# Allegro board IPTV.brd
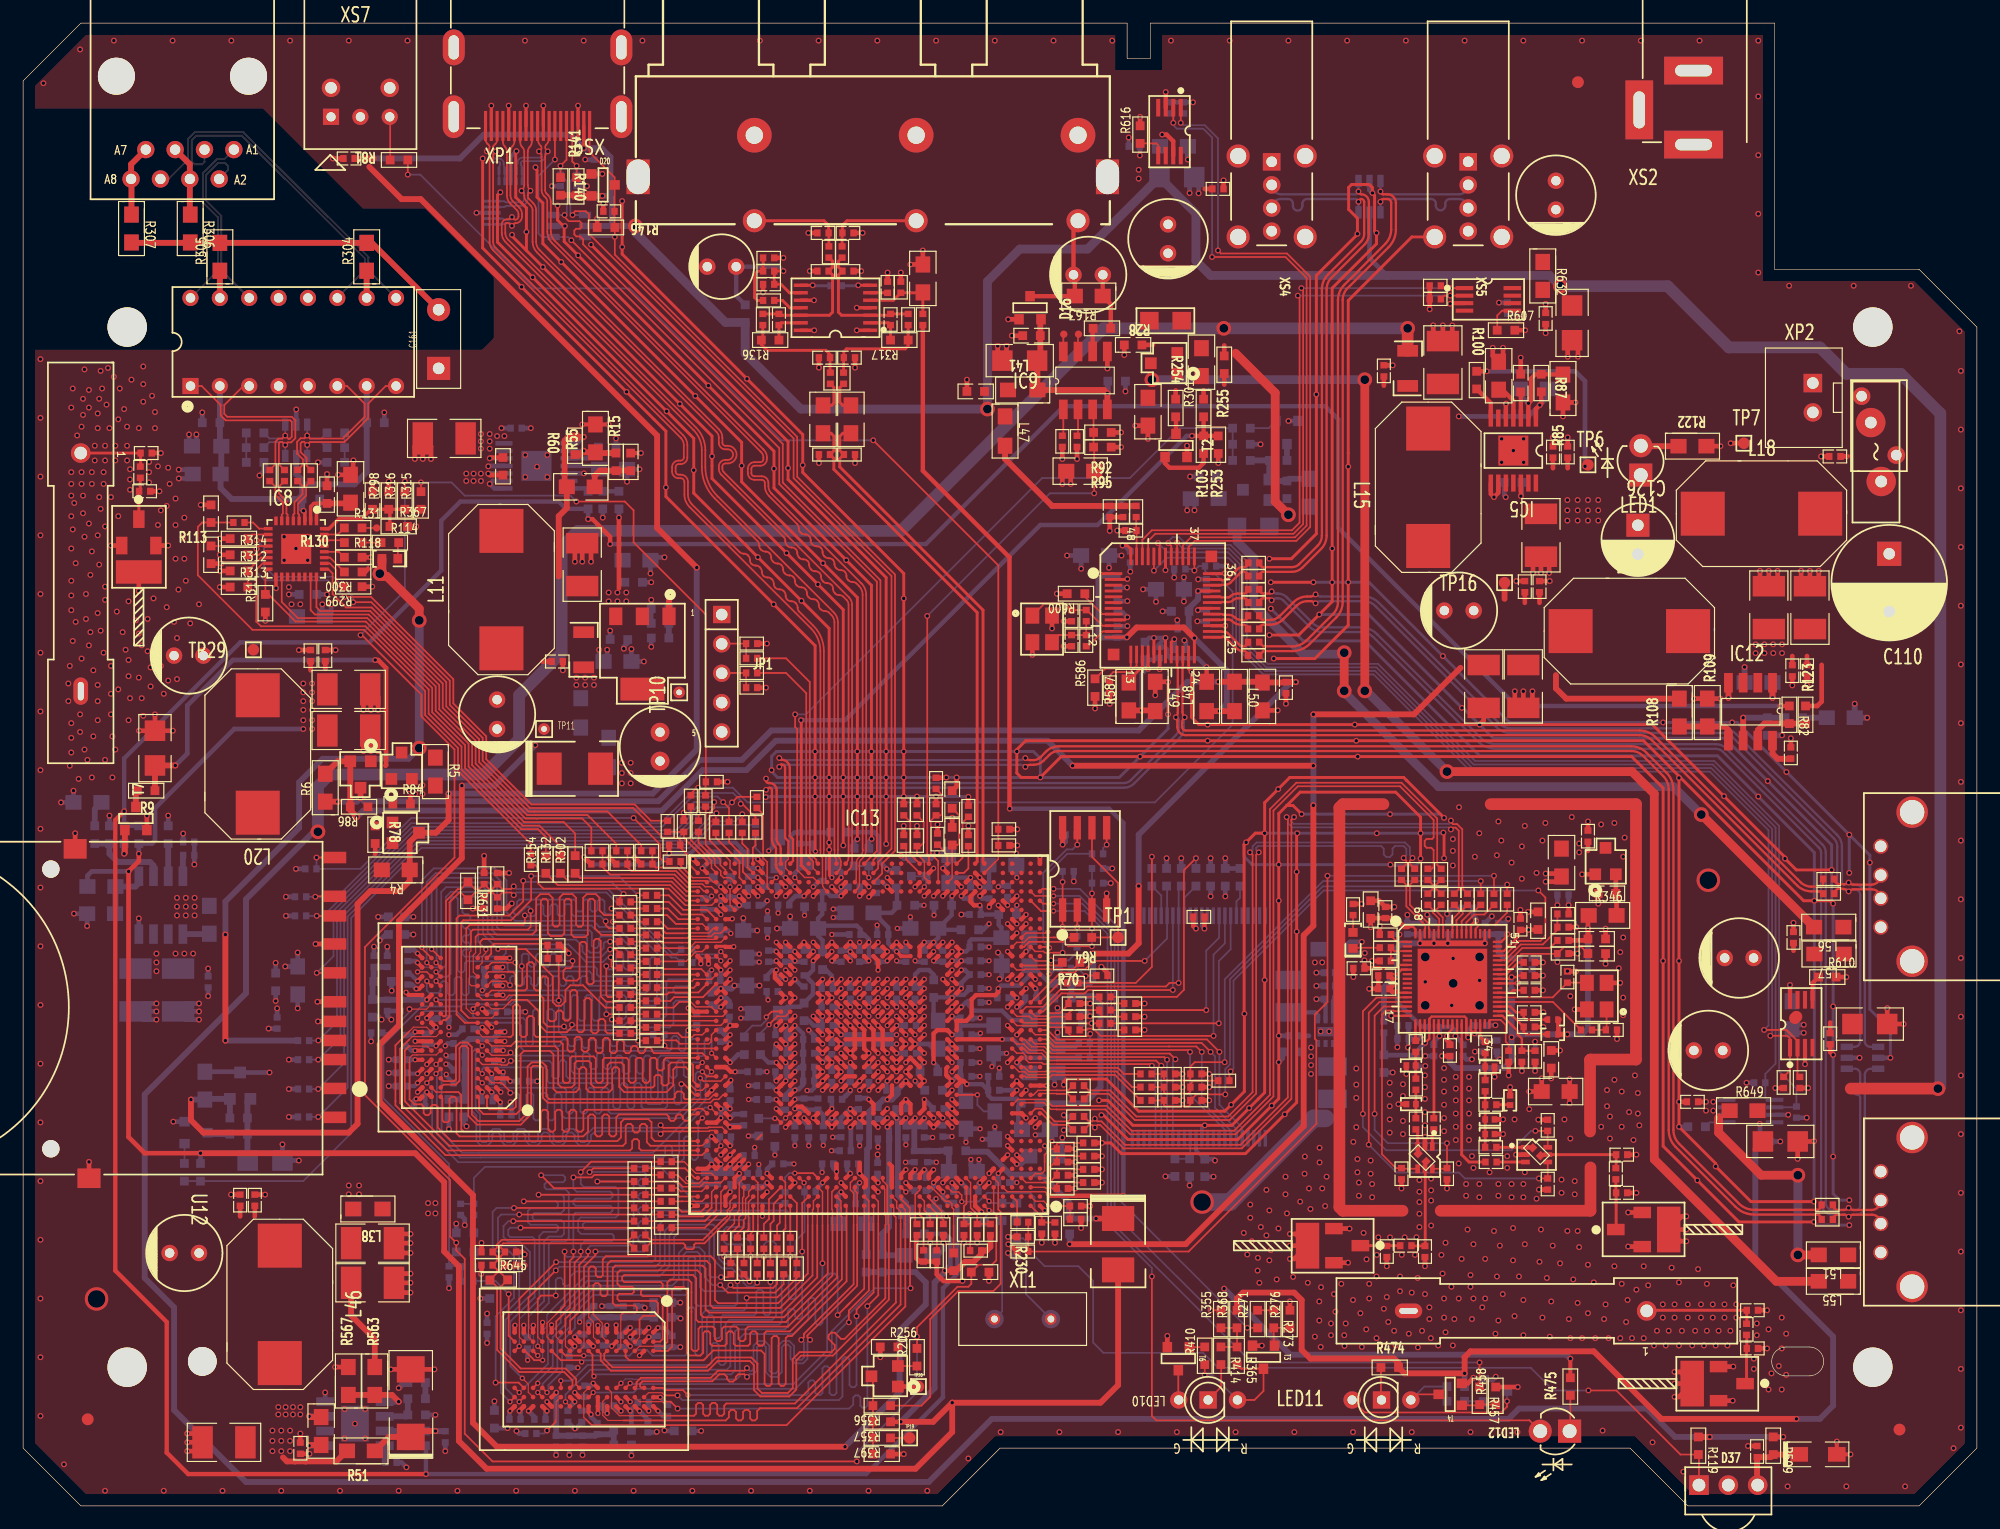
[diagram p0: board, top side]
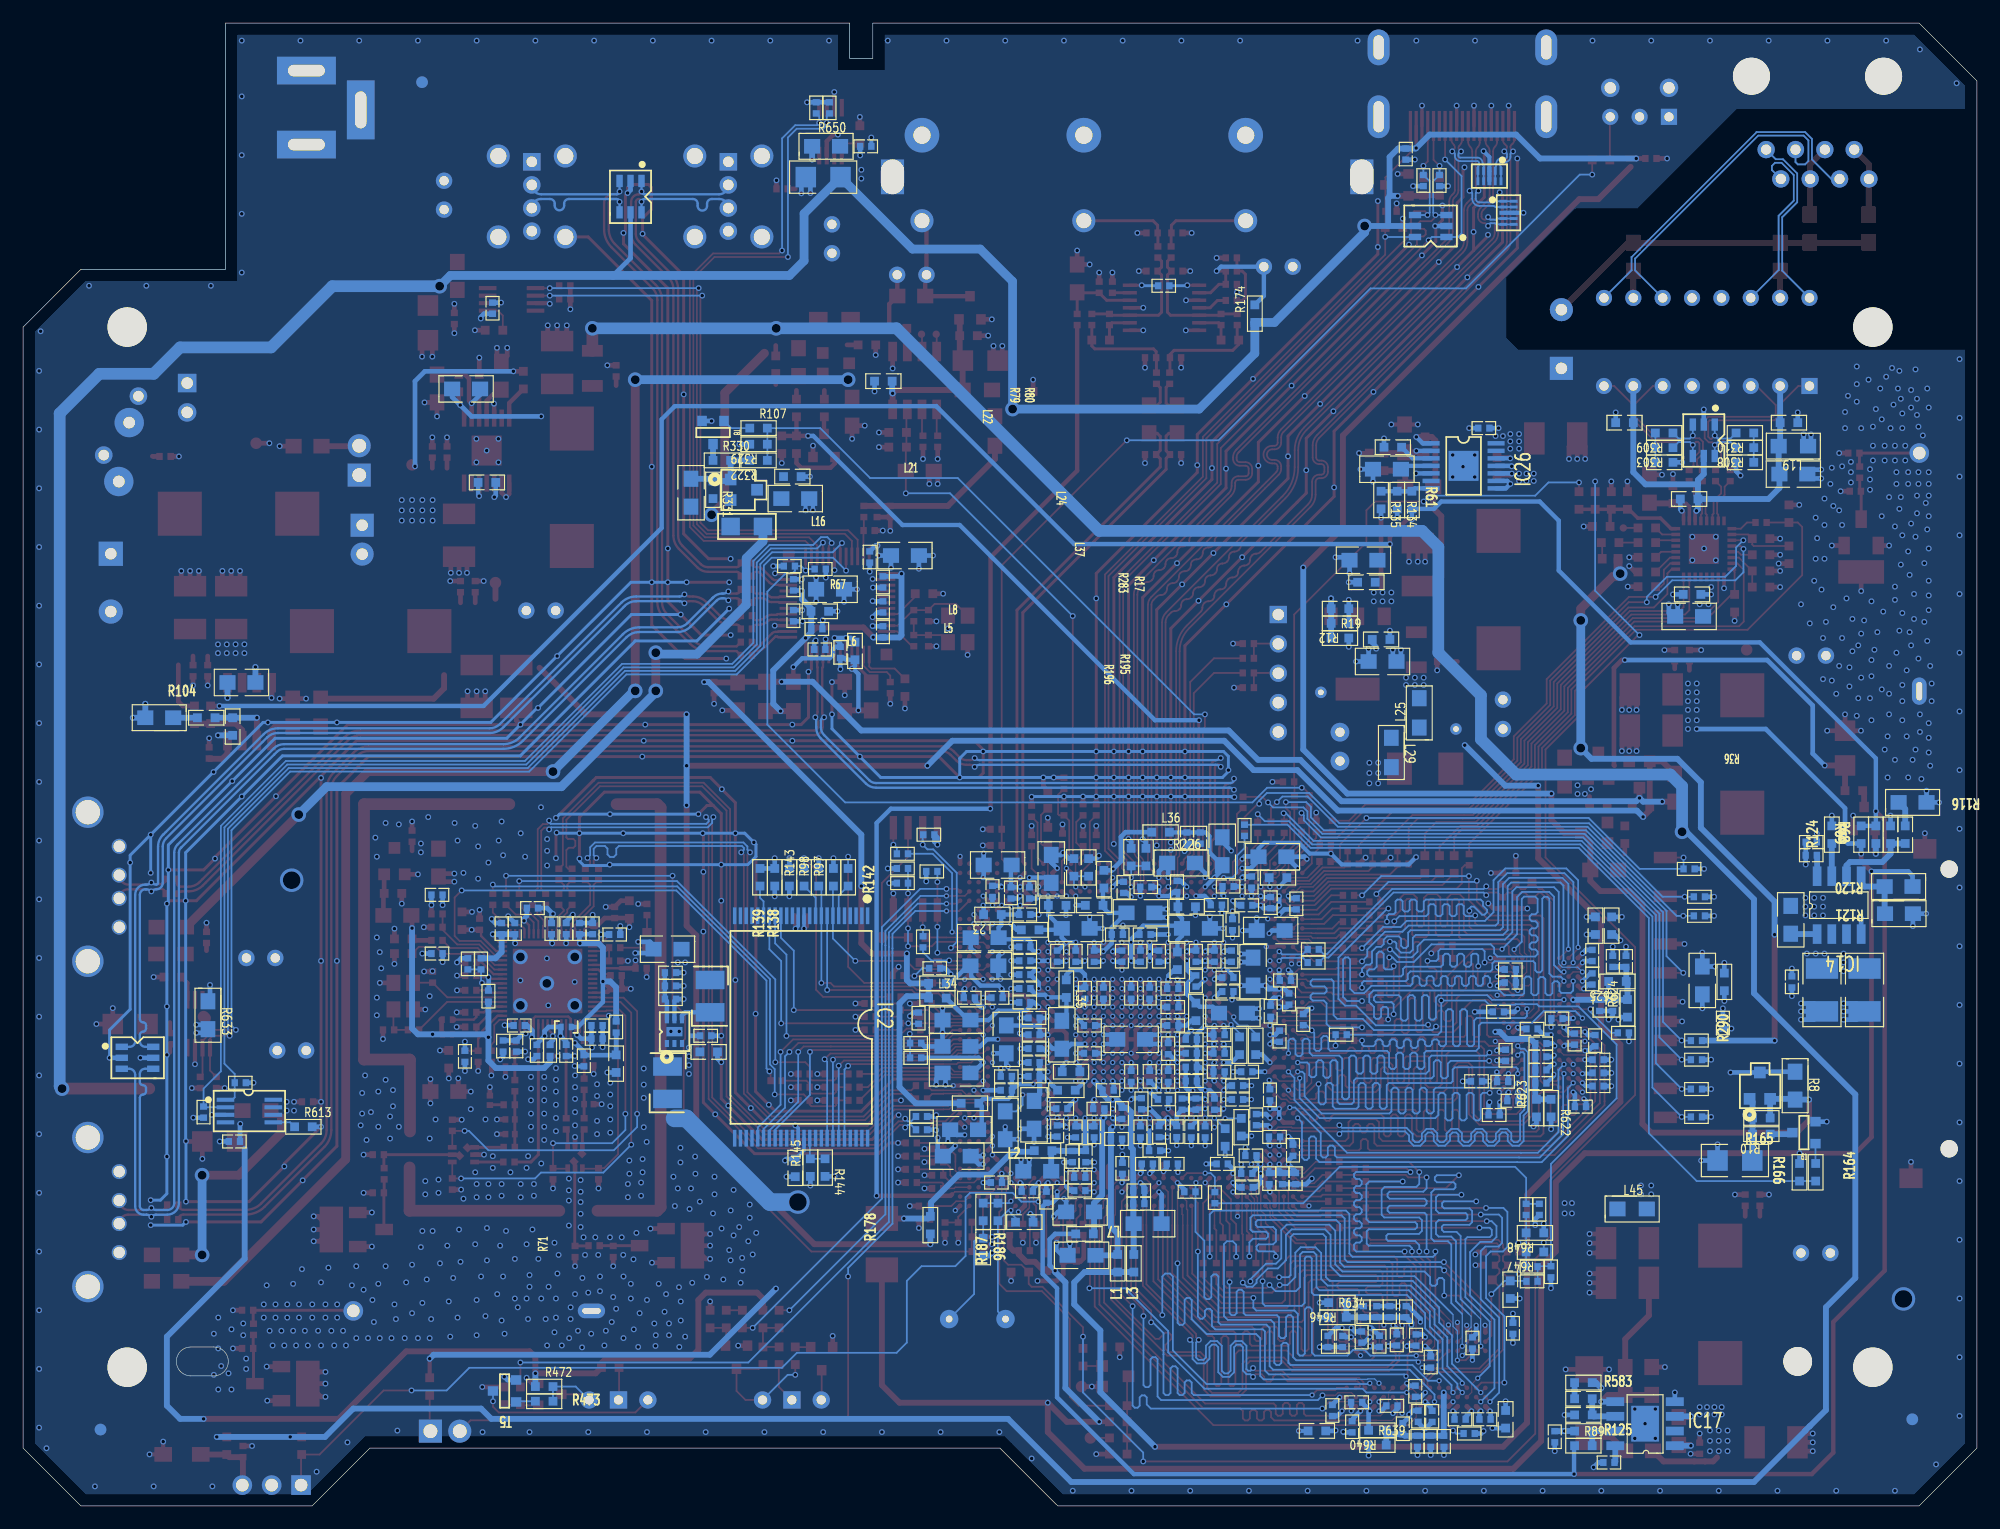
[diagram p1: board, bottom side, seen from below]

Outline 169 x 128.3 mm; copper layers: TOP, L02_P1, L03_P2, BOTTOM. Coordinates in mm from the lower left corner of the outline.
Outline path: 0,123.3 0,5 5,0 79.5,0 84.5,5 139,5 144,0 164,0 169,5 169,102 164,107 151.5,107 151.5,128.3 97.5,128.3 97.5,125.25 95.5,125.25 95.5,128.3 5,128.3 0,123.3 ; 152.5,13.75 154.5,13.75 arc(155.75,12.5) 154.5,11.25 152.5,11.25 arc(151.25,12.5) 152.5,13.75

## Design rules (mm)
net group N6210999: nets N6210999 N6211019
net group N6211183: nets N6211051 N6211183
net group N6376252: nets N6375056 N6376252
net group N6391887: nets N6391887 N6393086
net group N17621599: nets N17621599 N17621631
net group NF_ADNUM\G: nets NF_ADNUM\G TXD1_RMII0\G
net group NF_PAGE0\G: nets NF_PAGE0\G TXD0_RMII0\G
net group NF_PAGE1\G: nets NF_PAGE1\G TXEN_RMII0
net group RX-_PHY0\G: nets RX+_PHY0\G RX-_PHY0\G
net group SD_CCMD: nets N1109849 SD_CCMD
net group SD_CDATA2: nets N1103990 SD_CDATA2
net group TX+_PHY0\G: nets TX+_PHY0\G TX-_PHY0\G
net group 90OHM: nets DIFF_USB0D_N\G DIFF_USB0D_P\G N4126235 N4126359 N4126465 N4126501 N4127321 N4127377 N4127493 N4127601 USB1D_DM\G USB1D_DP\G USBHUB1_DM USBHUB1_DP USBHUB2_DM USBHUB2_DP USBHUB3_DM USBHUB3_DP USBHUB4_DM USBHUB4_DP
net group 100OHM_PH: nets DIFF_HDMI_0N\G DIFF_HDMI_0P\G DIFF_HDMI_1N\G DIFF_HDMI_1P\G DIFF_HDMI_2N\G DIFF_HDMI_2P\G DIFF_HDMI_CLKN\G DIFF_HDMI_CLKP\G
net group 100OHM_SP: nets DDRA_CKN0 DDRA_CKN0_R DDRA_CKP0 DDRA_CKP0_R DDRA_DQSN0 DDRA_DQSN1 DDRA_DQSP0 DDRA_DQSP1 DDRB_CKN0 DDRB_CKN0_R DDRB_CKP0 DDRB_CKP0_R DDRB_DQSN0 DDRB_DQSN1 DDRB_DQSP0 DDRB_DQSP1 N617373 N617477 N16928233 N16929752 PCIE_CLKOUTN PCIE_CLKOUTP PCIE_RDN PCIE_RDP PCIE_TDN PCIE_TDP
net group NET_3V3\G: nets 3V3\G
net group NET_3V3_MOS\G: nets 3V3_MOS\G
net group NET_5V0_MOS\G: nets 5V0_MOS\G
net group NET_12V\G: nets 12V\G
net group NET_GND: nets GND
net group NET_N2616386: nets N2616386
net group NET_VCC_3.3V: nets VCC_3.3V
net group NET_VCC_SCI\G: nets VCC_SCI\G
net group S10: nets DDRA_ADDR0 DDRA_ADDR0_R DDRA_ADDR1 DDRA_ADDR1_R DDRA_ADDR2 DDRA_ADDR2_R DDRA_ADDR3 DDRA_ADDR3_R DDRA_ADDR4 DDRA_ADDR4_R DDRA_ADDR5 DDRA_ADDR5_R DDRA_ADDR6 DDRA_ADDR6_R DDRA_ADDR7 DDRA_ADDR7_R DDRA_ADDR8 DDRA_ADDR8_R DDRA_ADDR9 DDRA_ADDR9_R DDRA_ADDR10 DDRA_ADDR10_R DDRA_ADDR11 DDRA_ADDR11_R DDRA_ADDR12 DDRA_ADDR12_R DDRA_ADDR13 DDRA_ADDR13_R DDRA_ADDR14 DDRA_ADDR14_R DDRA_BA0 DDRA_BA0_R DDRA_BA1 DDRA_BA1_R DDRA_BA2 DDRA_BA2_R DDRA_CASN DDRA_CASN_R DDRA_CKE0 DDRA_CSN0 DDRA_CSN0_R DDRA_DM0 DDRA_DM1 DDRA_DQ0 DDRA_DQ1 DDRA_DQ2 DDRA_DQ3 DDRA_DQ4 DDRA_DQ5 DDRA_DQ6 DDRA_DQ7 DDRA_DQ8 DDRA_DQ9 DDRA_DQ10 DDRA_DQ11 DDRA_DQ12 DDRA_DQ13 DDRA_DQ14 DDRA_DQ15 DDRA_ODT0 DDRA_ODT0_R DDRA_RASN DDRA_RASN_R DDRA_WEN DDRA_WEN_R DDRB_ADDR0 DDRB_ADDR0_R DDRB_ADDR1 DDRB_ADDR1_R DDRB_ADDR2 DDRB_ADDR2_R DDRB_ADDR3 DDRB_ADDR3_R DDRB_ADDR4 DDRB_ADDR4_R DDRB_ADDR5 DDRB_ADDR5_R DDRB_ADDR6 DDRB_ADDR6_R DDRB_ADDR7 DDRB_ADDR7_R DDRB_ADDR8 DDRB_ADDR8_R DDRB_ADDR9 DDRB_ADDR9_R DDRB_ADDR10 DDRB_ADDR10_R DDRB_ADDR11 DDRB_ADDR11_R DDRB_ADDR12 DDRB_ADDR12_R DDRB_ADDR13 DDRB_ADDR13_R DDRB_ADDR14 DDRB_ADDR14_R DDRB_BA0 DDRB_BA0_R DDRB_BA1 DDRB_BA1_R DDRB_BA2 DDRB_BA2_R DDRB_CASN DDRB_CASN_R DDRB_CKE0 DDRB_CSN0 DDRB_CSN0_R DDRB_DM0 DDRB_DM1 DDRB_DQ0 DDRB_DQ1 DDRB_DQ2 DDRB_DQ3 DDRB_DQ4 DDRB_DQ5 DDRB_DQ6 DDRB_DQ7 DDRB_DQ8 DDRB_DQ9 DDRB_DQ10 DDRB_DQ11 DDRB_DQ12 DDRB_DQ13 DDRB_DQ14 DDRB_DQ15 DDRB_ODT0 DDRB_ODT0_R DDRB_RASN DDRB_RASN_R DDRB_RESETN\G DDRB_WEN DDRB_WEN_R RESET_DDR3\G

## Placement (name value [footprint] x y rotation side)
ANT1  ANT_005-B  [JACK-COAXIAL-4P-NTPS1]  113.89 22.52 270 top
ANT2  ANT_005-B  [JACK-COAXIAL-4P-NTPS1]  139.55 23.91 90 top
ANT3  ANT_005-B  [JACK-COAXIAL-4P-NTPS1]  147.17 10.58 270 top
ANT4  ANT_005-B  [JACK-COAXIAL-4P-NTPS1]  10.01 83.6 0 top
ANT5  ANT_005B  [ANT-34X5-2P]  4.8 80.94 270 top
ANT6  ANT_005B  [ANT-34X5-2P]  130.28 17.06 180 top
C1  C0805-10V-475KX  [C0805]  88.27 37.47 0 bottom
C2  C0402-16V-104KX  [C0402]  76.75 39.17 180 bottom
C3  C0402-16V-104KX  [C0402]  69.95 37.16 90 bottom
C4  C0805-10V-475KX  [C0805]  60.94 56.17 180 bottom
C5  C0805-10V-475KX  [C0805]  88.24 30.26 180 bottom
C6  C0402-16V-104KX  [C0402]  69.95 39.57 90 bottom
C7  C0402-16V-104KX  [C0402]  77.09 30.23 270 bottom
C8  C0402-16V-104KX  [C0402]  75.55 44.37 270 bottom
C9  C0402-16V-104KX  [C0402]  71.55 44.37 270 bottom
C10  C0402-16V-104KX  [C0402]  69.55 44.77 180 bottom
C11  C0402-16V-104KX  [C0402]  71.55 37.16 90 bottom
C12  C0402-16V-104KX  [C0402]  64.79 45.71 180 bottom
C13  C0402-16V-104KX  [C0402]  76.75 41.57 180 bottom
C14  C0402-16V-104KX  [C0402]  73.15 37.16 90 bottom
C15  C0402-16V-104KX  [C0402]  84.81 27.98 0 bottom
C16  C0402-16V-104KX  [C0402]  73.15 44.37 270 bottom
C17  C0402-16V-104KX  [C0402]  77.15 44.37 270 bottom
C18  10UF  [C0805]  53.06 81.83 0 bottom
C19  C0805-10V-475KX  [C0805]  81.28 28.96 0 bottom
C20  C0805-10V-475KX  [C0805]  77.45 21.68 180 bottom
C21  C0402-16V-104KX  [C0402]  76.35 32.36 270 bottom
C22  C0402-16V-104KX  [C0402]  64.48 47.57 90 bottom
C23  C0805-10V-475KX  [C0805]  73.15 40.37 180 bottom
C24  C0805-10V-475KX  [C0805]  71.73 24.42 180 bottom
C25  C0805-10V-475KX  [C0805]  77.57 25.44 180 bottom
C26  C0805-10V-475KX  [C0805]  88.27 42.04 180 bottom
C27  10UF  [C0805]  51.41 73.06 180 bottom
C28  C0805-10V-475KX  [C0805]  79.15 40.77 90 bottom
C29  10N  [C0603]  51.54 74.97 180 bottom
C30  C0805-10V-475KX  [C0805]  65.28 56.64 90 bottom
C31  C0805-10V-475KX  [C0805]  64.35 42.64 0 bottom
C32  C/227M/X7R/6.3V/EC-2_5-6X12_5_LESR  [C-D6-2_54]  124.21 77.47 270 top
C33  C/227M/X7R/6.3V/EC-2_5-6X12_5_LESR  [C-D6-2_54]  14.33 73.57 270 top
C34  330N  [C0402]  70.33 105.57 180 bottom
C35  330N  [C0402]  74.78 105.45 270 top
C36  C/227M/X7R/6.3V/EC-2_5-6X12_5_LESR  [C-D6-2_54]  92.13 106.52 270 top
C37  C/227M/X7R/6.3V/EC-2_5-6X12_5_LESR  [C-D6-2_54]  13.95 21.88 270 top
C38  C0402-16V-104KX  [C0402]  77.6 28.42 180 bottom
C39  C0402-16V-104KX  [C0402]  79.55 32.44 90 bottom
C40  C0402-16V-104KX  [C0402]  74.42 31.75 0 bottom
C41  C0402-16V-104KX  [C0402]  75.95 34.36 180 bottom
C42  C0402-16V-104KX  [C0402]  69.55 41.57 0 bottom
C43  C1210-16V-106KX  [C1210]  151 77.72 270 top
C44  C0402-16V-104KX  [C0402]  153.03 72.26 90 top
C45  0603  [C0603]  52.81 79.92 180 bottom
C46  NC  [C0603]  55.09 77.63 0 bottom
C47  C/227M/X7R/6.3V/EC-2_5-6X12_5_LESR  [C-D6-2_54]  41 68.49 0 top
C48  C0805-10V-475KX  [C0805]  87.61 32.55 0 bottom
C49  C1210-16V-106KX  [C1210]  9.72 44.64 90 bottom
C50  C0402-16V-104KX  [C0402]  16 45.34 90 bottom
C51  C1210-16V-106KX  [C1210]  17.37 5.5 0 top
C52  C0402-16V-104KX  [C0402]  23.98 4.99 90 top
C53  10UF  [C0805]  77.83 106.21 90 top
C56  C0402-16V-104KX  [C0402]  82.35 43.57 180 bottom
C57  C0402-16V-104KX  [C0402]  82.35 44.77 180 bottom
C58  C0402-16V-104KX  [C0402]  67.18 57.78 270 bottom
C59  C0402-16V-104KX  [C0402]  68.33 57.78 270 bottom
C60  47PF  [C0402]  65.38 102.65 270 top
C61  C0402-16V-104KX  [C0402]  67.55 45.42 90 bottom
C62  47PF  [C0402]  75.03 102.65 90 top
C63  C0805-10V-475KX  [C0805]  81.55 33.84 270 bottom
C67  C0402-16V-104KX  [C0402]  81.55 38.36 180 bottom
C72  NC  [C0402]  90.15 46.52 180 bottom
C75  100NF  [C0402]  64.49 105.7 180 top
C77  C1210-16V-106KX  [C1210]  36.42 92.37 0 top
C78  C0603-10V-102KX  [C0603]  96.01 100.46 0 top
C79  C1210-16V-106KX  [C1210]  154.56 77.72 270 top
C80  C0402-16V-104KX  [C0402]  154.31 72.26 90 top
C81  C0402-16V-104KX  [C0402]  42.65 93.26 180 bottom
C82  C0805-50V-105ZY  [C0805]  97.29 94.68 90 top
C84  C1206-10V-106KX  [C1206]  86.21 99.1 180 top
C85  C0805-50V-105ZY  [C0805]  101.93 98.97 90 top
C86  C0402-16V-104KX  [C0402]  152.91 65.15 90 top
C87  C0805-50V-684ZY  [C0805]  48.24 88.18 0 top
C88  C0805-50V-105ZY  [C0805]  111.23 87.67 270 bottom
C89  C0603-16V-332KX  [C0603]  153.16 68.2 0 bottom
C90  C0603-16V-224KX  [C0603]  52.55 90.33 90 top
C91  C0603-10V-102KX  [C0603]  102.46 89.06 0 bottom
C92  C0805-50V-100JCG  [C0805]  130.68 96.65 180 bottom
C93  C0805-50V-103KX  [C0805]  150.11 71.25 0 bottom
C94  C0805-50V-332ZX  [C0805]  51.03 89.7 180 bottom
C95  C0805-50V-105ZY  [C0805]  102.21 87.16 0 bottom
C96  C0603-50V-104KX  [C0603]  82.4 96.43 180 top
C97  C0603-16V-104KX  [C0603]  41.5 89.95 270 top
C98  C1210-16V-106KX  [C1210]  131.29 83.98 90 top
C100  C1210-10V-226ZX  [C1210]  126.34 70.9 270 top
C102  C0603-50V-104KX  [C0603]  87.22 101.26 180 top
C106  C0402-16V-104KX  [C0402]  82.14 27.22 0 bottom
C107  C1210-10V-226ZX  [C1210]  48.36 81.44 270 top
C108  C0603-16V-105ZY  [C0603]  50.52 91.6 0 bottom
C109  C0402-16V-103KX  [C0402]  46.2 73.06 180 top
C110  CD11-100V-476  [C_500M_1000X1500P]  161.42 79.88 270 top
C111  C1210-16V-106KX  [C1210]  13.4 44.64 90 bottom
C112  C0402-16V-104KX  [C0402]  14.33 57.44 180 bottom
C113  0603  [C0603]  16.26 82.3 90 top
C114  1206  [C0805]  28.32 88.01 90 top
C115  C0402-16V-104KX  [C0402]  14.33 56.3 0 bottom
C116  C0603-16V-332KX  [C0603]  6.2 58.08 90 bottom
C117  NI_C0603-16V-332KX  [C0603]  7.47 58.08 90 bottom
C118  NI_C0603-16V-332KX  [C0603]  34.04 7.87 0 bottom
C119  C0402-16V-104KX  [C0402]  156.72 90.81 0 top
C120  C0805-50V-103KX  [C0805]  16.1 50.71 270 bottom
C121  C0402-16V-104KX  [C0402]  133.6 91.19 270 top
C122  C0402-16V-104KX  [C0402]  87.16 43.97 0 bottom
C123  C0402-16V-104KX  [C0402]  28.19 116.59 0 top
C124  C1210-10V-226ZX  [C1210]  28.17 70.65 0 top
C125  C0402-16V-104KX  [C0402]  63.15 51.97 0 bottom
C126  CD110-25V-107  [C_250M_630X1200P]  139.68 83.6 270 top
C127  C0402-16V-104KX  [C0402]  132.33 91.19 270 top
C128  C0402-16V-104KX  [C0402]  79.15 34.36 180 bottom
C130  C0402-16V-104KX  [C0402]  70.75 47.57 270 bottom
C131  C0402-16V-104KX  [C0402]  62.74 53.98 270 bottom
C132  C0402-16V-104KX  [C0402]  73.81 53.52 90 bottom
C133  C0402-16V-104KX  [C0402]  81.55 39.57 0 bottom
C134  0603  [C0603]  26.29 87.5 90 top
C135  C0402-16V-104KX  [C0402]  82.35 45.97 0 bottom
C136  1206  [C0805]  15.88 89.28 0 bottom
C137  0603  [C0603]  24.89 87.12 180 bottom
C138  C0402-16V-104KX  [C0402]  65.79 51.99 180 bottom
C139  C0402-16V-104KX  [C0402]  85.15 53.17 90 bottom
C142  C0402-16V-104KX  [C0402]  64.77 53.59 0 bottom
C143  1206  [C0805]  24.89 76.96 180 bottom
C144  C0402-16V-103KX  [C0402]  101.7 50.96 0 top
C145  C0402-16V-104KX  [C0402]  82.35 47.17 0 bottom
C146  100NF  [C0402]  21.97 41.78 270 bottom
C147  C0402-16V-104KX  [C0402]  67.55 47.57 270 bottom
C148  4.7UF  [C0805]  23.75 45.47 90 bottom
C149  0603  [C0603]  24.64 78.87 180 bottom
C150  C0402-16V-104KX  [C0402]  61.09 52.2 90 bottom
C151  0603  [C0603]  20.07 90.3 180 bottom
C152  0603  [C0603]  27.05 90.3 0 bottom
C153  0603  [C0603]  16.26 93.73 0 bottom
C154  C0402-16V-104KX  [C0402]  73.95 47.57 270 bottom
C155  C0402-16V-104KX  [C0402]  64.79 44.51 180 bottom
C156  C0402-16V-104KX  [C0402]  65.95 47.57 270 bottom
C157  C0402-16V-103KX  [C0402]  77.95 32.36 270 bottom
C158  C0402-16V-103KX  [C0402]  72.49 27.29 180 bottom
C159  C0402-16V-104KX  [C0402]  75.15 35.96 180 bottom
C160  0603  [C0603]  30.48 93.73 180 bottom
C161  -  [C_200_250]  35.94 98.42 90 top
C162  C0402-16V-104KX  [C0402]  72.49 26.15 180 bottom
C163  C0805-50V-332ZX  [C0805]  127.64 97.79 270 top
C165  C0603-16V-104KX  [C0603]  128.88 88.56 180 bottom
C167  C0603-16V-105ZY  [C0603]  129.54 97.16 90 top
C169  C1210-10V-226ZX  [C1210]  122.81 98.93 270 top
C171  C0402-16V-103KX  [C0402]  117.7 98.21 270 top
C173  C0402-16V-104KX  [C0402]  78.23 30.23 270 bottom
C174  NI_C0603-16V-332KX  [C0603]  150.88 67.44 270 bottom
C175  C0402-16V-104KX  [C0402]  73.95 33.96 270 bottom
C176  C0603-50V-104KX  [C0603]  94.59 97.32 0 bottom
C177  C0402-16V-104KX  [C0402]  69.55 43.17 0 bottom
C178  NC  [C0402]  90.91 43.47 0 top
C180  C0402-16V-104KX  [C0402]  83.95 37.16 180 bottom
C181  680PF  [C0402]  71.48 99.35 0 top
C182  680PF  [C0402]  69.32 99.35 180 top
C186  C0402-16V-104KX  [C0402]  83.95 35.96 180 bottom
C193  C/100pF/25V/NPO/0402  [C0402]  124.94 52.49 90 top
C194  C/100pF/25V/NPO/0402  [C0402]  123.8 52.49 90 top
C196  C0402-16V-104KX  [C0402]  81.55 37.16 180 bottom
C197  C0805-10V-475KX  [C0805]  85.85 46.74 180 bottom
C198  C0402-16V-104KX  [C0402]  84.75 43.97 180 bottom
C199  C0805-10V-475KX  [C0805]  83.95 40.37 270 bottom
C200  C0402-16V-104KX  [C0402]  81.55 42.22 180 bottom
C201  C0402-16V-104KX  [C0402]  81.55 40.77 180 bottom
C202  C0603-50V-102KX  [C0603]  80.37 61.12 270 top
C203  100UF  [C-D5XH11-2_5]  60.43 107.23 270 top
C205  C0603-50V-102KX  [C0603]  78.11 55.24 270 bottom
C207  C0603-50V-104KX  [C0603]  80.37 57.95 270 top
C208  C0603-16V-105ZY  [C0603]  102.72 54.39 90 bottom
C209  C0603-16V-105ZY  [C0603]  102.21 29.25 270 bottom
C210  C/106K/6.3V/X7R/0805  [C0805]  133.07 55.66 270 top
C211  C/106K/6.3V/X7R/0805  [C0805]  132.56 35.85 0 top
C212  C0603-50V-104KX  [C0603]  76.83 55.24 270 bottom
C213  C0805-10V-475KX  [C0805]  72.35 51.31 180 bottom
C214  C0805-10V-475KX  [C0805]  77.95 49.97 180 bottom
C215  C0603-16V-225KX  [C0603]  76.35 51.97 0 bottom
C216  C0402-16V-104KX  [C0402]  74.35 49.44 180 bottom
C217  C0603-16V-225KX  [C0603]  79.55 51.97 180 bottom
C218  C/104K/10V/X7R/0402  [C0402]  133.2 52.87 180 bottom
C219  C0402-16V-103KX  [C0402]  76.35 47.57 270 bottom
C220  C0402-16V-104KX  [C0402]  77.95 47.57 270 bottom
C221  C0402-16V-103KX  [C0402]  79.55 47.57 270 bottom
C222  C3216X7R1E106K  [C1206]  11.41 65.57 270 top
C223  C0402-16V-104KX  [C0402]  81.95 53.04 270 bottom
C224  C/18pF/J/50V/NPO/0402  [C0402]  137.39 41.19 0 top
C225  C0805-10V-475KX  [C0805]  80.07 55.12 90 bottom
C226  C0805-10V-475KX  [C0805]  85.83 49.17 0 bottom
C227  C0805-10V-475KX  [C0805]  67.55 49.97 180 bottom
C228  C/10pF/J/50V/NPO/0402  [C0402]  126.47 39.66 90 top
C229  C0402-16V-104KX  [C0402]  82.35 48.37 0 bottom
C230  C0402-16V-104KX  [C0402]  82.35 51.17 180 bottom
C231  C0603-16V-225KX  [C0603]  68.35 51.84 180 bottom
C232  C0402-16V-104KX  [C0402]  83.55 53.04 270 bottom
C233  C0402-16V-104KX  [C0402]  72.35 47.57 90 bottom
C234  C0805-10V-475KX  [C0805]  84.71 55.45 0 bottom
C235  C0402-16V-103KX  [C0402]  71.89 53.54 0 bottom
C236  C0402-16V-103KX  [C0402]  71.95 49.44 180 bottom
C237  C0402-16V-104KX  [C0402]  69.19 53.6 90 bottom
C238  C/10pF/J/50V/NPO/0402  [C0402]  126.98 29.76 180 top
C239  100N  [C0603]  30.23 87 90 top
C240  NIL/C/1pF/J/50V/NPO/0402  [C0402]  126.95 34.71 0 top
C241  C/104K/10V/X7R/0402  [C0402]  120.5 38.52 270 bottom
C242  C/8R0pF/J/50V/NPO/0402  [C0402]  133.58 45.76 90 top
C243  NI/47P/5%/0603  [C0603]  16.26 85.85 270 top
C244  C/104K/10V/X7R/0402  [C0402]  119.36 41.57 180 bottom
C245  C/475K/10V/X7R/0603  [C0603]  116.56 51.6 90 top
C246  C/104K/10V/X7R/0402  [C0402]  124.94 51.73 180 bottom
C247  C0402-16V-104KX  [C0402]  50.67 112.01 180 top
C248  C/475K/6.3V/X7R/0603  [C0603]  136.12 49.06 0 top
C249  C/4.7uF/6.3V/X7R/0603  [C0603]  117.7 38.26 90 bottom
C250  C/103K/16V/X7R/0402  [C0402]  130.28 47.03 0 top
C251  C0402-16V-104KX  [C0402]  49.4 116.97 270 bottom
C254  C/104K/10V/X7R/0402  [C0402]  123.29 49.95 90 bottom
C255  C3216X7R1E106K  [C1206]  20.93 29.88 180 bottom
C268  2.2UF  [C0805]  71.6 94.02 90 top
C272  C0603-50V-300JCG  [C0603]  82.4 24.55 180 bottom
C274  C0603-50V-300JCG  [C0603]  85.95 22.39 270 bottom
C275  C0402-16V-104KX  [C0402]  60.07 28.32 270 bottom
C276  C0402-16V-104KX  [C0402]  65.55 40.77 180 bottom
C277  C0402-16V-104KX  [C0402]  65.55 37.56 180 bottom
C278  C0402-16V-104KX  [C0402]  62.8 30.31 0 bottom
C279  C0402-16V-104KX  [C0402]  72.35 32.36 270 bottom
C280  C0402-16V-104KX  [C0402]  61.21 28.32 270 bottom
C281  C0402-16V-104KX  [C0402]  66.75 32.36 270 bottom
C282  C0402-16V-104KX  [C0402]  65.28 29.59 0 bottom
C283  C0402-16V-104KX  [C0402]  61.15 35.56 90 bottom
C284  C0402-16V-104KX  [C0402]  71.75 29.59 180 bottom
C285  C0402-16V-104KX  [C0402]  65.55 39.17 180 bottom
C286  C0402-16V-104KX  [C0402]  58.87 52.09 90 bottom
C287  C0402-16V-104KX  [C0402]  63.12 27.56 180 bottom
C288  C0402-16V-104KX  [C0402]  67.95 40.37 180 bottom
C289  C0402-16V-104KX  [C0402]  73.91 29.21 270 bottom
C290  C0402-16V-104KX  [C0402]  59.16 30.77 90 bottom
C291  C0402-16V-104KX  [C0402]  70.36 35.18 0 bottom
C292  C0402-16V-104KX  [C0402]  64.39 50.29 90 bottom
C293  C0402-16V-104KX  [C0402]  67.95 37.96 180 bottom
C294  C0402-16V-104KX  [C0402]  65.95 34.76 270 bottom
C295  C0402-16V-104KX  [C0402]  62.33 33.42 90 bottom
C296  C0805-10V-475KX  [C0805]  62.61 46.23 90 bottom
C297  C1210-10V-226ZX  [C1210]  28.17 67.09 0 top
C298  C0402-16V-104KX  [C0402]  63.15 28.76 0 bottom
C299  C0402-16V-104KX  [C0402]  58.93 28.32 270 bottom
C300  C0402-16V-104KX  [C0402]  59.82 45.47 180 bottom
C301  C0402-16V-104KX  [C0402]  63.95 36.36 180 bottom
C302  C0402-16V-104KX  [C0402]  63.15 37.56 0 bottom
C303  C0402-16V-104KX  [C0402]  59.5 43.86 270 bottom
C304  C0402-16V-104KX  [C0402]  61.09 42.8 90 bottom
C305  C0402-16V-104KX  [C0402]  63.95 35.16 180 bottom
C306  C0402-16V-104KX  [C0402]  71.12 30.73 180 bottom
C307  CA-C3216-16V-475M  [C3216P]  155.26 4.46 0 top
C308  C0402-16V-104KX  [C0402]  149.99 4.7 270 top
C309  C0402-16V-104KX  [C0402]  70.74 32.38 90 bottom
C310  C0402-16V-104KX  [C0402]  67.95 32.37 270 bottom
C311  C0402-16V-104KX  [C0402]  69.6 29.59 180 bottom
C312  C0402-16V-104KX  [C0402]  60.33 40.64 90 bottom
C313  C0805-10V-475KX  [C0805]  61.09 49.78 180 bottom
C314  C0402-16V-104KX  [C0402]  68.75 34.76 270 bottom
C315  C0402-16V-104KX  [C0402]  69.22 32.38 270 bottom
C316  C/104K/10V/X7R/0402  [C0402]  127.48 39.79 270 bottom
C317  C/104K/10V/X7R/0402  [C0402]  120.88 49.95 90 bottom
C318  C/104K/10V/X7R/0402  [C0402]  122.02 49.95 90 bottom
C319  C/2.2uF/10V/X7R/0603  [C0603]  137.01 53 0 top
C320  C/104K/10V/X7R/0402  [C0402]  122.02 39.41 270 bottom
C321  C/104K/10V/X7R/0402  [C0402]  119.74 49.95 90 bottom
C322  C/104K/10V/X7R/0402  [C0402]  124.56 39.41 270 bottom
C323  C/NIL  [C0402]  117.96 22.01 270 top
C324  C/10pF/J/50V/NPO/0402  [C0402]  137.77 28.74 90 top
C325  C/104K/10V/X7R/0402  [C0402]  130.28 41.44 180 top
C326  C/104K/16V/X7R/0402  [C0402]  130.53 46.9 90 bottom
C327  C/10pF/J/50V/NPO/0402  [C0402]  120.46 39.76 90 top
C328  C/104K/16V/X7R/0402  [C0402]  117.7 45.88 180 top
C329  C/104K/10V/X7R/0402  [C0402]  130.28 42.71 180 top
C330  C/104K/16V/X7R/0402  [C0402]  117.83 51.35 90 top
C331  C/104K/16V/X7R/0402  [C0402]  117.7 44.74 180 top
C332  C/10pF/J/50V/NPO/0402  [C0402]  126.95 31.03 180 top
C333  C/104K/16V/X7R/0402  [C0402]  129.52 50.33 90 top
C334  C/10pF/J/50V/NPO/0402  [C0402]  122.02 33.06 90 top
C335  C/100pF/J/50V/NPO/0402  [C0402]  113.01 46.14 0 bottom
C336  C/475K/6.3V/X7R/0603  [C0603]  136.12 47.79 0 top
C337  NIL/C/10pF/J/50V/NPO/0402  [C0402]  119.23 28.74 90 top
C338  1NF  [C0603]  82.78 20.23 0 top
C339  C/105M/6.3V/X7R/0402  [C0402]  135.36 57.95 270 top
C340  C/104K/10V/X7R/0402  [C0402]  130.28 45.88 0 top
C341  C0805-50V-220JCG  [C0805]  91.44 89.53 180 top
C342  C/104K/16V/X7R/0402  [C0402]  115.55 46.52 180 top
C343  C/104K/16V/X7R/0402  [C0402]  127.61 49.95 90 bottom
C344  NIL/C/10pF/J/50V/NPO/0402  [C0402]  123.17 28.74 90 top
C345  C/104K/10V/X7R/0402  [C0402]  117.83 49.44 0 bottom
C346  CA-C6032-25V-106M  [C6032P]  33.53 8.89 90 top
C347  C0402-16V-104KX  [C0402]  36.51 5.98 90 bottom
C348  C0402-16V-104KX  [C0402]  31.83 3.76 0 bottom
C349  C0603-16V-332KX  [C0603]  34.04 9.27 0 bottom
C350  C0805-50V-103KX  [C0805]  25.78 6.48 270 top
C351  C1210-10V-226ZX  [C1210]  30.23 19.3 0 top
C352  C1210-10V-226ZX  [C1210]  30.23 22.73 0 top
C353  C1210-10V-226ZX  [C1210]  129.77 70.9 270 top
C354  C0402-16V-103KX  [C0402]  18.77 26.45 90 top
C355  C/105M/6.3V/X7R/0402  [C0402]  123.42 39.41 90 top
C356  C/104K/J/50V/X7R/0402  [C0402]  121.51 52.49 90 top
C357  C/104K/J/50V/X7R/0402  [C0402]  122.66 52.49 90 top
C358  C/104K/J/50V/X7R/0402  [C0402]  91.29 35.22 180 top
C359  C/104K/J/50V/X7R/0402  [C0402]  91.29 36.36 180 top
C360  C/104K/16V/X7R/0402  [C0402]  126.47 49.95 90 bottom
C361  NIL/C/10pF/J/50V/NPO/0402  [C0402]  131.88 32.93 270 top
C362  C/104K/10V/X7R/0402  [C0402]  119.36 40.42 180 bottom
C363  C/104K/10V/X7R/0402  [C0402]  130.79 38.9 90 bottom
C364  C/475K/10V/X7R/0603  [C0603]  131.04 50.63 90 top
C365  C/104K/16V/X7R/0402  [C0402]  129.64 38.9 270 top
C366  NIL/C/10pF/J/50V/NPO/0402  [C0402]  131.88 27.85 90 top
C367  C/105M/6.3V/X7R/0402  [C0402]  130.28 44.61 0 top
C368  C/104K/16V/X7R/0402  [C0402]  109.96 40.68 180 bottom
C369  C/104K/10V/X7R/0402  [C0402]  133.2 47.79 180 bottom
C370  C/104K/10V/X7R/0402  [C0402]  126.34 39.79 270 bottom
C371  C/2.2uF/10V/X7R/0603  [C0603]  132.18 38.65 270 top
C372  C/10pF/J/50V/NPO/0402  [C0402]  119.61 22.52 0 top
C373  C/10pF/J/50V/NPO/0402  [C0402]  120.47 33.06 90 top
C374  C/104K/10V/X7R/0402  [C0402]  126.09 41.57 0 bottom
C375  C/NIL  [C0402]  121.26 22.01 270 top
C376  C/NIL  [C0402]  138.28 27.09 0 top
C377  C/NIL  [C0402]  138.28 30.39 0 top
C378  C/475K/10V/X7R/0603  [C0603]  109.7 39.28 180 bottom
C379  C/106K/10V/X7R/0805  [C0805]  113.26 48.17 0 bottom
C380  C0402-16V-104KX  [C0402]  20.04 26.45 90 top
C381  C0402-16V-104KX  [C0402]  24.87 73.57 90 top
C382  C0402-16V-103KX  [C0402]  26.14 73.57 90 top
C383  C0402-16V-104KX  [C0402]  129.9 79.54 90 top
C384  C0402-16V-103KX  [C0402]  131.17 79.54 90 top
C385  C/NIL  [C0402]  149.58 13.63 0 top
C386  C/NIL  [C0402]  149.58 16.93 0 top
C387  C/10pF/J/50V/NPO/0402  [C0402]  149.07 15.28 90 top
C388  C/NIL  [C0402]  10.52 87.79 0 top
C389  C/NIL  [C0402]  10.64 91.1 0 top
C390  C/10pF/J/50V/NPO/0402  [C0402]  10.14 89.45 90 top
C391  100NF  [C0603]  74.27 4.48 0 top
C392  1NF  [C0402]  71.35 110.15 180 top
C393  2.2UF  [C0805]  69.19 94.02 270 top
C394  1NF  [C0402]  69.19 110.15 0 top
C404  RMEMK105BJ104KV_FR  [C0402]  93.99 86.04 270 top
C405  CEJMK212BJ106KD_T  [C0402]  95.14 86.04 270 top
C406  CEJMK212BJ106KD_T  [C0805]  92.72 82.23 0 bottom
C407  CEJMK212BJ106KD_T  [C0805]  99.2 79.31 0 bottom
C408  RMEMK105BJ104KV_FR  [C0402]  102.37 77.02 270 bottom
C409  RMEMK105BJ104KV_FR  [C0402]  100.09 74.1 0 bottom
C410  RMEMK105BJ104KV_FR  [C0402]  95.77 82.1 270 bottom
C411  RMEMK105BJ104KV_FR  [C0402]  94.63 77.79 90 bottom
C412  GRM31CR602J226ME19L  [C0402]  100.34 75.88 0 bottom
C413  RMEMK105BJ104KV_FR  [C0402]  98.31 73.85 90 bottom
C414  CM105X5R475M06AT  [C0603]  97.04 73.98 90 bottom
C415  C1608X7R1H104KT000N  [C0603]  100.09 77.4 180 bottom
C416  RMEMK105BJ104KV_FR  [C0402]  109.23 70.8 270 top
C417  CEJMK212BJ106KD_T  [C0805]  107.2 70.04 90 top
C418  GRM155R71C103KA01D  [C0402]  102.72 81.32 0 bottom
C419  RMEMK105BJ104KV_FR  [C0402]  94.63 79.94 270 bottom
C420  RMEMK105BJ104KV_FR  [C0402]  94.63 75.63 90 bottom
C421  RMEMK105BJ104KV_FR  [C0402]  102.37 79.69 90 bottom
C422  C0402C180J5GAC_7867  [C0402]  90.69 77.02 270 top
C423  C0402C180J5GAC_7867  [C0402]  90.69 74.86 270 top
C424  C0402C104K8PAC_7867  [C0402]  128.4 103.63 270 bottom
C425  UVZ1C221MED1TD  [C-D6_3XH11-2_5]  132.59 113.41 0 top
C426  C0402C104K8PAC_7867  [C0402]  131.7 102.74 270 top
C427  1206X106M250CT  [C1206]  133.99 102.36 270 top
C428  UVZ1C221MED1TD  [C-D6_3XH11-2_5]  148.44 47.41 270 top
C429  C0402C104K8PAC_7867  [C0402]  156.31 40.42 270 top
C430  1206X106M250CT  [C1206]  159.74 41.69 0 top
C431  C0402C104K8PAC_7867  [C0402]  153.14 49.19 90 top
C432  UVZ1C221MED1TD  [C-D6_3XH11-2_5]  145.77 39.41 270 top
C433  C0402C104K8PAC_7867  [C0402]  150.72 31.53 0 bottom
C434  1206X106M250CT  [C1206]  151.99 31.53 0 top
C435  C0402C104K8PAC_7867  [C0402]  144.4 34.96 180 top
C436  UVZ1C221MED1TD  [C-D6_3XH11-2_5]  99.04 109.64 0 top
C437  C0402C104K8PAC_7867  [C0402]  96.11 117.64 180 bottom
C438  1206X106M250CT  [C1206]  99.8 114.97 0 bottom
C439  C0402C104K8PAC_7867  [C0402]  103.35 113.96 0 top
C441  C0402C104K8PAC_7867  [C0402]  33.02 40.26 270 bottom
C442  C0402C104K8PAC_7867  [C0402]  36.32 42.16 0 bottom
C443  C0402C104K8PAC_7867  [C0402]  33.27 45.59 90 bottom
C444  C0402C104K8PAC_7867  [C0402]  33.27 47.62 90 bottom
C445  C0402C104K8PAC_7867  [C0402]  32.77 38.61 180 bottom
C446  C0402C104K8PAC_7867  [C0402]  34.8 40.39 90 bottom
C447  C0402C104K8PAC_7867  [C0402]  41.02 36.7 0 bottom
C448  C0402C104K8PAC_7867  [C0402]  40.13 35.05 180 bottom
C449  C0402C104K8PAC_7867  [C0402]  40.77 38.99 270 bottom
C450  C1608X5R0J106MT0A0E  [C0603]  31.6 50.2 90 bottom
C451  C0402C104K8PAC_7867  [C0402]  32.77 36.32 180 bottom
C452  C0402C104K8PAC_7867  [C0402]  34.29 34.54 180 bottom
C453  C0402C104K8PAC_7867  [C0402]  32.77 37.47 180 bottom
C454  C0402C104K8PAC_7867  [C0402]  40.36 46.42 180 bottom
C455  C0402C104K8PAC_7867  [C0402]  40.36 45.27 180 bottom
C456  C0402C104K8PAC_7867  [C0402]  43.28 36.74 0 bottom
C457  C0402C104K8PAC_7867  [C0402]  38.48 41.27 180 bottom
C458  C0402C104K8PAC_7867  [C0402]  41.76 33.82 0 bottom
C459  C0402C104K8PAC_7867  [C0402]  41.39 42.75 0 bottom
C460  C1608X5R0J106MT0A0E  [C0603]  33 50.2 90 bottom
C461  C0402C104K8PAC_7867  [C0402]  37.72 40.01 180 bottom
C462  CV05X5R105K10AH  [C0402]  37.72 38.86 180 bottom
C463  C0402C104K8PAC_7867  [C0402]  37.72 37.72 180 bottom
C464  C0402C104K8PAC_7867  [C0402]  37.72 36.58 0 bottom
C465  C0402C104K8PAC_7867  [C0402]  32.64 43.31 270 bottom
C466  CV05X5R105K10AH  [C0402]  31.5 43.31 270 bottom
C467  C0402C104K8PAC_7867  [C0402]  30.35 47.12 90 bottom
C468  C0402C104K8PAC_7867  [C0402]  31.5 47.12 270 bottom
C469  C0402C104K8PAC_7867  [C0402]  47.24 5.59 270 bottom
C470  CV05X5R105K10AH  [C0402]  46.1 5.59 270 bottom
C471  C0402C104K8PAC_7867  [C0402]  48.39 5.59 270 bottom
C472  C0402C104K8PAC_7867  [C0402]  49.66 6.68 270 bottom
C473  C/1NF/0603  [C0603]  40.36 18.71 270 bottom
C474  C0402C104K8PAC_7867  [C0402]  53.06 16.8 90 bottom
C475  CV05X5R105K10AH  [C0402]  51.92 16.8 90 bottom
C476  C0402C104K8PAC_7867  [C0402]  43.64 14.1 270 bottom
C477  C0402C104K8PAC_7867  [C0402]  56.13 14.22 270 bottom
C478  C0402C104K8PAC_7867  [C0402]  50.78 16.8 90 bottom
C479  C0402C104K8PAC_7867  [C0402]  54.86 14.22 270 bottom
C480  C0402C104K8PAC_7867  [C0402]  51.68 14.24 90 bottom
C481  C0402C104K8PAC_7867  [C0402]  49.38 16.8 270 bottom
C482  C0402C104K8PAC_7867  [C0402]  47.24 12.45 270 bottom
C483  C0402C104K8PAC_7867  [C0402]  47.12 7.75 270 bottom
C484  C0402C104K8PAC_7867  [C0402]  55.75 8.26 270 bottom
C485  C0402C104K8PAC_7867  [C0402]  48.33 7.76 270 bottom
C486  C0402C104K8PAC_7867  [C0402]  54.04 6.84 270 bottom
C487  C0402C104K8PAC_7867  [C0402]  53.21 14.61 90 bottom
C488  C0402C104K8PAC_7867  [C0402]  50.18 14.36 270 bottom
C489  C0402C104K8PAC_7867  [C0402]  48.58 9.92 270 bottom
C490  C0402C104K8PAC_7867  [C0402]  48.51 14.35 90 bottom
C491  C0402C104K8PAC_7867  [C0402]  44.7 7.49 180 bottom
C492  C0402C104K8PAC_7867  [C0402]  42.55 7.49 180 bottom
C493  C0402C104K8PAC_7867  [C0402]  40.13 15.37 90 bottom
C494  C0402C104K8PAC_7867  [C0402]  50.6 8.66 180 bottom
C495  C0402C104K8PAC_7867  [C0402]  53.65 8.96 0 bottom
C496  C1608X5R0J106MT0A0E  [C0603]  57.09 6.49 0 bottom
C497  C1608X5R0J106MT0A0E  [C0603]  40.77 7.49 270 bottom
C0603  C/1NF/0603  [C0402]  45.85 48.51 0 top
CAP3  100U/25  [C-D6_3XH12-2_5]  55.09 65.7 0 top
D5  1N4004  [D-6_86X4_06]  94.72 22.64 180 top
D6  1N4004  [D-6_86X4_06]  47.73 63.79 270 top
D10  NC  [R0402]  46.48 114.68 90 bottom
D11  NC  [R0402]  47.88 114.68 90 bottom
D16  BAV99  [SOT23_2]  87.1 103.67 90 top
D20  BAV99  [SOT23_2]  50.16 114.3 0 top
D37  TSOP34338  [D_TSOP34XXX]  144.96 1.8 0 top
FB1  FB/600ohm+-25%,0.65ohm,0.2A/0402/murata  [L0402]  122.02 41.44 90 bottom
FB2  FB/600ohm+-25%,0.65ohm,0.2A/0402/murata  [L0402]  132.31 42.07 270 top
FB3  FB/600ohm+-25%,0.65ohm,0.2A/0402/murata  [L0402]  132.31 40.8 270 top
FB4  FB/600ohm+-25%,0.65ohm,2A/1206  [L1210]  113.26 36.61 180 bottom
IC2  NAND01GW3B2CN5E  [SOP48_050_1840_2000M]  101.7 41.44 270 bottom
IC5  -  [SOP14_065_440_640M_EXP]  128.91 91.31 270 top
IC8  KSZ8041NL  [MLF32_050M]  23.62 82.8 270 top
IC9  NCS2553DG  [SOP8_127_390_600M]  91.88 97.38 90 top
IC12  MP1482DS  [SOP8_127_390_600M]  149.42 68.72 270 top
IC13  HI3716C  [BGA756_080M_38X38]  73.15 40.77 180 top
IC14  MP1482DS  [SOP8_127_390_600M]  11.91 51.98 90 bottom
IC17  MP1484EN-LF-Z  [SOP8_127_390_600M_EXP]  28.7 7.11 0 bottom
IC26  -  [SOP14_065_440_640M_EXP]  44.4 89.99 180 bottom
JP1  SINGLE_ROW_PIN40T  [JP_1X5_100]  60.43 72.05 0 top
L1  BLM11A601SPT-L0603  [L0603]  74.32 20.99 270 bottom
L2  BLM11A601SPT-L0603  [L0603]  80.77 30.73 0 bottom
L3  BLM11A601SPT-L0603  [L0603]  72.92 20.99 270 bottom
L5  L0603-BLM11A601SPT  [L0603]  78.75 35.96 180 bottom
L6  L0603-BLM11A601SPT  [L0603]  87.1 34.84 0 bottom
L7  BLM11A601SPT-L0603  [L0603]  77.19 23.53 0 bottom
L8  L0603-BLM11A601SPT  [L0603]  78.35 37.56 180 bottom
L10  PBO3316-100MT  [L_DO3316]  138.94 75.69 180 top
L11  PBO3316-3R3MT  [L_DO3316]  41.38 79.29 270 top
L12  MPZ1206S101A  [L1206]  119.76 98.42 180 top
L14  MPZ1206S101A  [L1206]  48.49 74.08 0 top
L15  PBO3316-3R3MT  [L_DO3316]  121.54 88.14 90 top
L16  L0603-BLM11A601SPT  [L0603]  89.92 45.21 0 bottom
L18  PBO3316-100MT  [L_DO3316]  150.37 85.85 180 top
L19  L_0805  [L0805]  15.88 91.69 0 bottom
L20  PBO3316-100MT  [L_DO3316]  20.3 65.06 90 top
L21  L0603-BLM11A601SPT  [L0603]  81.89 49.85 180 bottom
L22  L0603-BLM11A601SPT  [L0603]  75.51 54.23 270 bottom
L23  SM-R-C0603-471J  [R0603]  85.15 51.17 0 bottom
L24  L0603-BLM11A601SPT  [L0603]  69.15 47.17 270 bottom
L25  NI/MPZ2012S101A  [L0805]  48.24 68.62 90 bottom
L26  NIL/2nH  [IND-0402]  120.05 38.11 0 top
L29  220ohm-0.05ohm-2A-0805  [L0805]  50.65 65.19 270 bottom
L31  NIL/2nH  [IND-0402]  126.87 38.01 180 top
L34  L0603-BLM11A601SPT  [L0603]  89.92 43.94 180 bottom
L35  L0603-BLM11A601SPT  [L0603]  78.77 44.75 270 bottom
L36  L0603-BLM11A601SPT  [L0603]  70.61 58.29 180 bottom
L37  L0603-BLM11A601SPT  [L0603]  67.55 42.75 270 bottom
L38  MPZ2012S101A  [L0805]  29.82 25.69 0 top
L39  NIL/2nH  [IND-0402]  126.87 33.44 180 top
L40  NIL/1.nH  [IND-0402]  128.63 35.09 270 top
L41  BLM21P331SG  [L0805]  86.46 96.56 180 top
L42  NIL/1.8nH  [IND-0402]  126.87 32.17 180 top
L43  L/2.2uH/10%/2A  [L1210]  109.58 44.11 0 bottom
L44  NIL/2nH  [IND-0402]  120.07 34.76 0 top
L45  MPZ2012S101A  [L0805]  29.82 25.69 180 bottom
L46  PBO3316-100MT  [L_DO3316]  22.2 17.44 90 top
L47  MGLB2012_220T_LF  [L0805]  84.94 93 270 top
L48  MGLB2012_220T_LF  [L0805]  102.37 70.04 90 top
L49  MGLB2012_220T_LF  [L0805]  97.93 70.04 270 top
L50  MGLB2012_220T_LF  [L0805]  104.79 70.04 270 top
L51  MGLB2012_220T_LF  [L0805]  156.59 21.72 180 top
L55  NI/MGLB2012_220T_LF  [L0805]  156.59 19.43 180 top
L56  NI/MGLB2012_220T_LF  [L0805]  156.19 50.08 180 top
L57  MGLB2012_220T_LF  [L0805]  156.21 47.75 180 top
LED1  2EF511  [LED_254M_3MM]  139.93 89.19 90 top
LED5  LED_0603  [LED0603]  31.73 81.95 90 top
LED8  LED/RED/2.0V,20mA/RAD-2.54mm/RoHS)  [LED0603]  115.04 48.93 0 top
LED10  209SURSYGW-S530  [D_LAMP_209SURSYGW]  102.5 9.17 180 top
LED11  209SURSYGW-S530  [D_LAMP_209SURSYGW]  117.5 9.17 180 top
LED12  2EF611  [LED_254M_3MM]  133.77 6.47 180 top
M*  -  [unnamed#2]  15.5 12.5 0 top
MARK1  MARK  [FILDMC_40]  134.49 123.19 0 top
MARK2  MARK  [FILDMC_40]  5.59 7.49 0 top
MARK3  MARK  [FILDMC_40]  162.31 6.6 0 top
MARK4  MARK  [FILDMC_40]  134.49 123.19 180 bottom
MARK5  MARK  [FILDMC_40]  5.59 7.49 180 bottom
MARK6  MARK  [FILDMC_40]  162.31 6.6 180 bottom
NOREF  -  []  -89.09 -134.56 90 top
NOREF#2  -  []  -79.09 13.44 0 top
NOREF#3  -  []  -89.09 -134.56 0 top
NOREF#4  -  []  10.6 -197.9 0 top
NOREF#5  -  []  -45.91 -197.9 0 top
NOREF#6  -  []  116.91 13.44 90 top
NOREF#7  -  []  -107.51 -242.35 0 top
NOREF#8  -  []  -62.87 22.86 0 top
Q5  IRLML6401PBF  [SOT-23-3P]  33.1 58.24 180 top
Q6  IRLML6401PBF  [SOT-23-3P]  32.74 64.05 270 top
Q7  IRLML6401PBF  [SOT-23-3P]  29.19 63.28 90 top
Q8  IRLML6401PBF  [SOT-23-3P]  98.69 98.87 0 top
Q9  IRLML6401PBF  [SOT-23-3P]  18.77 36.36 270 bottom
Q10  IRLML6401PBF  [SOT-23-3P]  106.66 87.92 0 bottom
R4  NI/SM-R-C0805-0R0J  [R0805]  32.23 55.03 180 top
R5  NI/SM-R-C0805-0R0J  [R0805]  35.66 63.54 270 top
R6  NI/SM-R-C0805-0R0J  [R0805]  26.14 62.14 90 top
R7  47K  [R0402]  64.49 104.3 180 top
R8  NI/SM-R-C0805-0R0J  [R0805]  15.72 36.36 270 bottom
R9  SM-R-C0603-101J  [R0603]  10.64 61.89 0 top
R10  SM-R-C0603-101J  [R0603]  18.64 32.17 0 bottom
R12  10R  [R0603]  55.09 76.36 0 bottom
R15  SM-R-C0603-393J  [R0603]  51.28 90.33 90 top
R16  NIL/PTC_16R090B  [R-7_4X3-5_1-2P]  160.53 93.47 90 top
R17  SM-R-R0603-680J  [R0603]  62.38 39.81 270 bottom
R18  PTC_LP30-250  [F-11_7X3-5_1-2P]  160.27 91.19 90 top
R19  121  [R0603]  55.09 75.09 180 bottom
R20  100  [R0603]  77.32 12.86 90 top
R28  SM-R-C0603-75R0F  [R0603]  93.32 101.89 0 top
R29  R/220/0402/5%  [R0402]  115.04 51.6 90 top
R36  SM-R-C0603-0R0J  [R0603]  60.45 54.36 180 bottom
R37  NC  [R0402]  93.32 45.88 0 top
R38  NC  [R0402]  95.73 43.47 0 top
R39  SM-R-R0402-472J  [R0402]  95.73 42.33 0 top
R40  NI/SM-R-R0402-472J  [R0402]  90.91 42.33 0 top
R41  SM-R-R0402472J  [R0402]  95.73 41.19 0 top
R42  SM-R-R0402-472J  [R0402]  91.54 42.2 90 bottom
R43  SM-R-R0402-472J  [R0402]  82.4 22.08 0 top
R44  SM-R-R0402-472J  [R0402]  81.38 23.91 270 top
R45  SM-R-R0402-472J  [R0402]  84.84 58.55 0 top
R46  SM-R-R0402-472J  [R0402]  84.84 57.15 0 top
R47  SM-R-R0402-472J  [R0402]  83.67 23.91 270 top
R48  SM-R-R0402-472J  [R0402]  82.53 23.91 270 top
R49  SM-R-R0402-472J  [R0402]  89.89 28.61 0 top
R50  SM-R-R0402-472J  [R0402]  92.18 29.12 180 top
R51  SM-R-C0805-0R0J  [R0805]  29.22 4.76 180 top
R52  SM-R-R0402-472J  [R0402]  89.89 30.9 0 top
R53  SM-R-R0402-472J  [R0402]  92.18 31.41 180 top
R54  SM-R-R0402-472J  [R0402]  89.89 27.47 0 top
R55  SM-R-C0805-2212F  [R0805]  49.51 92.37 270 top
R56  SM-R-R0402-472J  [R0402]  92.18 27.98 180 top
R57  SM-R-R0402-0R0J  [R0402]  90.91 41.19 180 top
R58  SM-R-R0402-0R0J  [R0402]  93.57 42.9 180 top
R59  NC  [R0402]  93.57 44.04 180 top
R60  SM-R-C0603-9761F  [R0603]  47.73 91.73 90 top
R61  SM-R-C0603-0R0J  [R0603]  48.87 87.03 90 bottom
R62  NC  [R0402]  90.78 45.25 180 top
R63  SM-R-R0402-0R0J  [R0402]  93.57 41.76 180 top
R64  SM-R-C0603-472J  [R0603]  91.67 49.19 0 top
R65  SM-R-R0402-330J  [R0402]  91.29 32.55 0 top
R66  SM-R-R0402330J  [R0402]  91.29 33.69 0 top
R67  SM-R-R0805-1910F  [R0805]  88.27 39.75 0 bottom
R68  SM-R-C0603-102J  [R0603]  10.01 58.08 90 bottom
R69  SM-R-C0603-103J  [R0603]  8.74 58.08 90 bottom
R70  SM-R-C0603-101J  [R0603]  90.65 47.03 180 top
R71  SM-R-R0805-1910F  [R0805]  84.05 32.93 270 bottom
R72  SM-R-R0402-49R9F  [R0402]  91.29 32.55 180 bottom
R73  SM-R-R0402-49R9F  [R0402]  91.29 33.69 180 bottom
R74  RT0402BRD075K1L  [R0402]  77.32 60.24 270 top
R75  RT0402BRD075K1L  [R0402]  78.97 62.52 270 top
R76  SM-R-C0402-112J  [R0402]  77.32 57.57 270 top
R77  SM-R-C0402-112J  [R0402]  78.97 60.24 270 top
R78  SM-R-C0603-103J  [R0603]  30.46 58.08 270 top
R79  SM-R-C0603-513J  [R0603]  73.15 56.13 90 bottom
R80  SM-R-C0603-682J  [R0603]  71.88 56.13 90 bottom
R81  SM-R-C0603-471J  [R0603]  32.51 116.46 180 top
R82  SM-R-C0603-0R0J  [R0603]  152.78 68.45 270 top
R83  NI/SM-R-R0402-472J  [R0402]  91.8 38.77 180 bottom
R84  NI/SM-R-C0603-103J  [R0603]  32.74 60.74 0 top
R85  SM-R-C0805-2212F  [R0805]  133.2 96.68 90 top
R86  NI/SM-R-C0603-103J  [R0603]  29.06 60.49 180 top
R87  SM-R-C0603-124J  [R0603]  131.32 97.16 270 top
R88  1K  [R0402]  77.83 102.65 90 top
R89  SM-R-C0603-0R0J  [R0603]  34.04 5.21 180 bottom
R90  20K  [R0402]  69.83 97.57 270 top
R91  SM-R-R0402-472J  [R0402]  101.45 36.23 0 top
R92  SM-R-C0603-75R0F  [R0603]  93.36 92.88 0 top
R93  NI/SM-R-R0402-472J  [R0402]  99.16 36.23 180 top
R94  NI/SM-R-R0402-472J  [R0402]  101.45 35.09 0 top
R95  SM-R-C0603-75R0F  [R0603]  93.36 91.61 0 top
R96  SM-R-R0402-472J  [R0402]  101.45 37.38 0 top
R97  SM-R-C0603-472J  [R0603]  98.91 54.39 90 bottom
R98  SM-R-C0603-472J  [R0603]  100.18 54.39 90 bottom
R99  SM-R-R0402-472J  [R0402]  86.46 22.01 180 top
R100  SM-R-C0603-1003F  [R0603]  125.73 97.41 270 top
R101  SM-R-R0402-472J  [R0402]  63.02 74.61 0 top
R102  NI/SM-R-R0402-472J  [R0402]  86.46 23.28 0 top
R103  SM-R-C0603-102J  [R0603]  102.11 91.82 90 top
R104  SM-R-C0805-222J  [R0805]  157.23 68.2 0 bottom
R105  NI_SM-R-C1206-0R0J  [R1206]  98.82 102.55 270 top
R106  NI/SM-R-R0402-472J  [R0402]  99.16 37.38 180 top
R107  SM-R-C0603-102J  [R0603]  105.39 93.26 180 bottom
R108  SM-R-C0805-1692F  [R0805]  143.27 68.64 270 top
R109  SM-R-C0805-1002F  [R0805]  145.68 68.64 90 top
R110  NI_SM-R-C1206-0R0J  [R1206]  106.4 84.75 90 bottom
R111  SM-R-R0402-472J  [R0402]  63.02 70.8 0 top
R112  RCR0402FR_07100R  [R0402]  91.16 48.81 90 bottom
R113  6.49K/1%  [R0603]  18.67 83.69 180 top
R114  0603  [R0603]  31.73 83.35 0 top
R115  R/1K/0402  [R0402]  89.89 92.11 90 top
R116  SM-R-C0805-222J  [R0805]  5.56 60.87 180 bottom
R117  R/1K/0402  [R0402]  91.16 92.11 90 top
R118  0603  [R0603]  28.55 82.08 0 top
R119  SM-R-C0603-103J  [R0603]  144.91 5.21 270 top
R120  RS05K2612FT  [R0805]  6.77 53.59 0 bottom
R121  SM-R-C0805-1002F  [R0805]  6.74 51.24 180 bottom
R122  SM-R-C0805-152J  [R0805]  144.4 91.69 0 top
R123  NI/SM-R-C0603-104J  [R0603]  154.18 68.45 90 top
R124  SM-R-C0603-104J  [R0603]  12.55 58.08 90 bottom
R125  NI/SM-R-C0603-104J  [R0603]  34.04 6.48 0 bottom
R126  RC0402JR_070R  [R0402]  24.89 89.15 90 top
R127  RC0402JR_070R  [R0402]  23.75 89.15 90 top
R128  RC0402JR_070R  [R0402]  22.61 89.15 90 top
R129  RC0402JR_070R  [R0402]  21.34 89.15 90 top
R130  RC0603JR_07330R  [R0603]  28.55 83.35 0 top
R131  RC0603JR_07330R  [R0603]  28.55 84.62 0 top
R132  0603  [R0603]  46.48 55.5 90 top
R133  NC/100K  [R0402]  69.19 106.84 180 top
R134  NC  [R0603]  50.14 87.03 270 bottom
R135  NC  [R0603]  51.54 87.03 270 bottom
R136  5.1K  [R0603]  64.62 100.88 180 top
R137  20K  [R0402]  70.97 97.57 90 top
R138  SM-R-C0603-102J  [R0603]  103.99 54.39 90 bottom
R139  SM-R-C0603-472J  [R0603]  105.26 54.39 270 bottom
R140  SM-R-C0603-202J  [R0603]  46.48 114.17 270 top
R141  SM-R-C0603-202J  [R0603]  47.88 114.17 270 top
R142  SM-R-C0603-0R0J  [R0603]  97.64 54.39 90 bottom
R143  SM-R-C0603-0R0J  [R0603]  101.45 54.39 90 bottom
R144  SM-R-C0603-472J  [R0603]  99.63 29.27 270 bottom
R145  SM-R-C0603-102J  [R0603]  100.9 29.27 90 bottom
R146  SM-R-C0603-103J  [R0603]  50.42 110.62 180 top
R147  SM-R-R0402-561J  [R0402]  24.26 33.66 180 bottom
R148  SM-R-R0402-102J  [R0402]  24.26 36.07 180 bottom
R149  SM-R-R0402-102J  [R0402]  24.26 38.61 180 bottom
R150  SM-R-R0402-102J  [R0402]  24 51.05 180 bottom
R151  SM-R-R0402-102J  [R0402]  24 52.7 180 bottom
R152  SM-R-R0402-102J  [R0402]  24.89 55.12 180 bottom
R153  SM-R-R0402-102J  [R0402]  24.26 40.26 180 bottom
R154  0603  [R0603]  45.21 55.5 90 top
R155  SM-R-R0402-472J  [R0402]  91.8 40.04 180 bottom
R157  RCR0402FR_07100R  [R0402]  92.94 56.43 180 bottom
R160  SM-R-R0402-0R0J  [R0402]  61.06 58.71 90 top
R163  NI/SM-R-C0603-0R  [R0805]  92.18 104.69 180 top
R164  SM-R-C0603-103J  [R0603]  13.95 28.87 270 bottom
R165  SM-R-C0603-103J  [R0603]  18.64 33.57 180 bottom
R166  SM-R-C0603-102J  [R0603]  15.34 28.87 270 bottom
R167  SM-R-R0402-472J  [R0402]  90.4 54.9 0 bottom
R168  NI/SM-R-R0402-472J  [R0402]  92.94 55.16 0 bottom
R169  SM-R-R0402-472J  [R0402]  92.94 53.89 180 bottom
R170  SM-R-R0402-472J  [R0402]  90.65 58.08 180 bottom
R171  SM-R-C0402-102J  [R0402]  81.76 57.57 270 top
R172  SM-R-C0402-102J  [R0402]  81.76 60.11 270 top
R173  SM-R-C0402-102J  [R0402]  79.1 57.7 270 top
R174  10  [R0603]  62.46 103.16 90 bottom
R175  NC/470K  [R0402]  71.48 90.97 0 top
R176  SM-R-C0402-102J  [R0402]  76.18 57.57 90 top
R177  SM-R-C0402-102J  [R0402]  76.18 60.24 90 top
R178  NC  [R0603]  90.53 24.29 90 bottom
R186  SM-R-R0603-105J  [R0603]  84.68 25.44 90 bottom
R187  SM-R-R0603-101J  [R0603]  85.95 25.44 90 bottom
R188  SM-R-R0402-103J  [R0402]  58.27 42.07 270 bottom
R189  NC  [R0402]  54.99 40.77 180 bottom
R190  SM-RC0402-2210F  [R0402]  60.75 31.93 0 bottom
R191  SM-R-C0402-102J  [R0402]  67.95 36.76 180 bottom
R192  SM-R-C0402-102J  [R0402]  67.95 39.17 0 bottom
R193  NC  [R0402]  65.91 26.67 270 bottom
R194  SM-RC0402-2210F  [R0402]  77.6 27.28 0 bottom
R195  SM-R-C0603-680J  [R0603]  63.63 32.77 270 bottom
R196  SM-R-C0603-680J  [R0603]  65.02 31.88 270 bottom
R197  SM-R-R0402-103J  [R0402]  68.07 27.18 0 bottom
R198  SM-R-C0402-102J  [R0402]  67.55 34.76 270 bottom
R199  SM-R-C0402-102J  [R0402]  72.26 34.8 90 bottom
R200  RK73B1ETTP330J  [R0402]  54.36 45.97 0 top
R201  RK73B1ETTP330J  [R0402]  54.36 52.83 0 top
R202  RK73B1ETTP330J  [R0402]  52.07 52.26 0 top
R203  RK73B1ETTP330J  [R0402]  54.36 51.69 0 top
R204  RK73B1ETTP330J  [R0402]  52.07 49.97 0 top
R205  RK73B1ETTP330J  [R0402]  54.36 50.55 0 top
R206  RK73B1ETTP330J  [R0402]  52.07 51.12 0 top
R207  RK73B1ETTP330J  [R0402]  54.36 49.4 0 top
R208  RK73B1ETTP330J  [R0402]  52.07 48.83 0 top
R209  RK73B1ETTP330J  [R0402]  54.36 48.26 0 top
R210  RK73B1ETTP330J  [R0402]  52.07 47.69 0 top
R211  RK73B1ETTP330J  [R0402]  54.36 47.12 0 top
R212  RK73B1ETTP330J  [R0402]  52.07 46.55 0 top
R213  RK73B1ETTP330J  [R0402]  54.36 44.83 0 top
R214  RK73B1ETTP330J  [R0402]  52.07 44.26 0 top
R215  RK73B1ETTP330J  [R0402]  52.07 45.4 0 top
R216  RK73B1ETTP330J  [R0402]  54.36 43.69 0 top
R217  RK73B1ETTP330J  [R0402]  52.07 43.12 0 top
R218  RK73B1ETTP330J  [R0402]  54.36 42.55 0 top
R219  RK73B1ETTP330J  [R0402]  52.07 41.97 0 top
R220  RK73B1ETTP330J  [R0402]  54.36 41.4 0 top
R221  RK73B1ETTP330J  [R0402]  52.07 40.89 0 top
R222  SM-R-R0402-472J  [R0402]  89.89 29.76 0 top
R223  NI/SM-R-R0402-472J  [R0402]  89.26 24.04 270 top
R224  SM-R-R0402-472J  [R0402]  57.15 58.8 90 top
R225  SM-R-R0402-472J  [R0402]  49.63 55.54 180 top
R226  SM-R-C0805-430J  [R0805]  68.83 55.63 180 bottom
R227  SM-R-R0402-472J  [R0402]  53.95 55.54 180 top
R228  SM-R-R0402-472J  [R0402]  51.79 55.54 180 top
R229  NI/SM-R-R0402-472J  [R0402]  92.18 30.26 0 top
R230  SM-R-R0603-472J  [R0603]  80.49 21.12 270 top
R231  RK73B1ETTP330J  [R0402]  54.36 40.26 0 top
R232  SM-R-R0402-330J  [R0402]  43.92 55.92 90 top
R233  SM-R-R0402-472J  [R0402]  56.36 57.19 180 top
R234  SM-R-R0402-330J  [R0402]  49.63 56.68 180 top
R235  SM-R-R0402-330J  [R0402]  51.79 56.68 180 top
R236  SM-R-R0402-330J  [R0402]  53.95 56.68 180 top
R237  SM-R-R0402-330J  [R0402]  59.92 58.71 90 top
R238  SM-R-R0402-330J  [R0402]  62.21 58.71 90 top
R239  SM-R-R0402-330J  [R0402]  58.42 58.8 90 top
R240  SM-R-R0402-0R0J  [R0402]  18.67 85.09 0 top
R241  SM-R-R0402-0R0J  [R0402]  56.39 55.75 180 top
R242  SM-R-R0402-330J  [R0402]  55.75 58.8 90 top
R244  SM-R-R0402-472J  [R0402]  77.32 23.91 270 top
R245  SM-R-R0402-472J  [R0402]  79.03 21.63 270 top
R246  4.7K  [R0402]  75.92 105.45 90 top
R247  5.6K  [R0402]  64.49 106.84 0 top
R248  SM-R-R0402-472J  [R0402]  77.89 21.63 270 top
R249  SM-R-R0402-102J  [R0402]  78.46 23.91 270 top
R250  SM-R-R0402-103J  [R0402]  79.6 23.91 270 top
R251  NI/SM-R-R0402-472J  [R0402]  80.49 26.71 90 bottom
R252  R/0/0402/1%  [R0402]  120.47 36.49 90 top
R253  SM-R-C0603-103J  [R0603]  103.38 91.82 270 top
R254  SM-R-C0603-103J  [R0603]  99.69 95 90 top
R255  SM-R-C0603-103J  [R0603]  103.9 98.74 90 top
R256  100K  [R0603]  74.91 13.75 0 top
R257  560  [R0402]  70.84 108.5 270 top
R258  2.2K  [R0402]  64.49 107.99 180 top
R259  0R/5%/0402  [R0402]  57.4 48.16 0 bottom
R260  0R/5%/0402  [R0402]  57.4 47.02 0 bottom
R261  RK73B1ETTP330J  [R0402]  65.79 20.52 90 top
R262  RK73B1ETTP330J  [R0402]  55.63 26.35 0 top
R263  RK73B1ETTP330J  [R0402]  53.34 25.78 0 top
R264  RK73B1ETTP330J  [R0402]  55.63 25.21 0 top
R265  RK73B1ETTP330J  [R0402]  64.07 22.73 90 top
R266  RK73B1ETTP330J  [R0402]  53.34 24.64 0 top
R267  RK73B1ETTP330J  [R0402]  65.21 22.73 90 top
R268  RK73B1ETTP330J  [R0402]  55.63 24.07 0 top
R269  RK73B1ETTP330J  [R0402]  55.63 28.64 0 top
R270  RK73B1ETTP330J  [R0402]  64.64 20.52 90 top
R271  SM-R-C0603-0R0J  [R0603]  106.78 16.17 90 top
R272  RK73B1ETTP330J  [R0402]  60.64 22.73 90 top
R273  SM-R-C0603-102J  [R0603]  108.18 16.17 270 top
R274  RK73B1ETTP330J  [R0402]  53.34 29.21 0 top
R275  RK73B1ETTP330J  [R0402]  66.36 22.73 90 top
R276  SM-R-C0603-472J  [R0603]  109.58 16.17 90 top
R277  RK73B1ETTP330J  [R0402]  61.79 22.73 90 top
R278  RK73B1ETTP330J  [R0402]  55.63 29.78 0 top
R279  RK73B1ETTP330J  [R0402]  66.93 20.52 90 top
R280  RK73B1ETTP330J  [R0402]  63.5 20.52 90 top
R281  RK73B1ETTP330J  [R0402]  55.63 27.5 0 top
R282  0R/5%/0402  [R0402]  53.34 23.44 0 top
R283  SM-R-R0603-680J  [R0603]  63.78 39.81 270 bottom
R284  RK73B1ETTP330J  [R0402]  62.93 22.73 90 top
R285  RK73B1ETTP330J  [R0402]  53.34 28.07 0 top
R286  0R/5%/0402  [R0402]  53.34 22.3 0 top
R287  RK73B1ETTP330J  [R0402]  62.36 20.52 90 top
R288  RK73B1ETTP330J  [R0402]  61.21 20.52 90 top
R289  RK73B1ETTP330J  [R0402]  53.34 26.92 0 top
R290  1K  [R0603]  21.84 45.34 270 bottom
R292  SM-R-R0402-330J  [R0402]  63.48 60.87 90 top
R293  NI/SM-R-R0402-472J  [R0402]  91.03 24.8 0 top
R294  SM-R-R0402-103J  [R0402]  63.35 58.46 90 bottom
R295  SM-R-R0402-472J  [R0402]  88.11 24.04 270 top
R296  SM-R-R0402-330J  [R0402]  63.35 58.71 90 top
R297  SM-R-R0402-472J  [R0402]  91.03 25.95 0 top
R298  10K  [R0603]  31.62 87 90 top
R299  0603  [R0603]  28.55 79.54 180 top
R300  0603  [R0603]  28.55 80.81 180 top
R301  NI/SM-R-C0603-103J  [R0603]  102.11 95 90 top
R302  0603  [R0603]  47.75 55.5 90 top
R303  75R/5%/0603  [R0603]  27.05 91.57 0 bottom
R304  75R/5%/0805  [R0805]  29.72 108.08 90 top
R305  75R/5%/0805  [R0805]  17.02 108.08 90 top
R306  75R/5%/0805  [R0805]  14.45 110.53 270 top
R307  75R/5%/0805  [R0805]  9.37 110.53 270 top
R308  75R/5%/0603  [R0603]  20.07 91.57 0 bottom
R309  75R/5%/0603  [R0603]  27.05 92.84 0 bottom
R310  75R/5%/0603  [R0603]  20.07 92.84 0 bottom
R311  0603  [R0603]  20.95 78.11 90 top
R312  RC0603JR_0710K  [R0603]  18.67 80.9 0 top
R313  NC/4.7K  [R0603]  18.67 79.5 0 top
R314  RC0603JR_074K7  [R0603]  18.67 82.3 0 top
R315  NC  [R0603]  34.42 87 90 top
R316  33R  [R0603]  33.02 87 90 top
R317  5.1K  [R0603]  75.79 100.88 180 top
R318  R/0/0402/1%  [R0402]  117.7 41.44 270 bottom
R319  R/0/0402/5%  [R0402]  128.37 52.49 90 top
R320  NIL/R/0/0402/1%  [R0402]  133.2 47.79 180 top
R321  R/0/0402/1%  [R0402]  130.79 38.9 90 top
R322  NI/SM-R-C0603-103J  [R0603]  105.39 90.46 0 bottom
R323  R/0/0402/5%  [R0402]  97.13 35.09 0 top
R324  R/0/0402/5%  [R0402]  103.86 36.79 180 top
R325  R/0/0402/5%  [R0402]  97.13 36.23 0 top
R326  R/0/0402/1%  [R0402]  128.75 44.11 90 bottom
R327  NI/R/0/0402/5%  [R0402]  86.46 24.55 0 top
R328  R/0/0402/5%  [R0402]  97.13 37.38 0 top
R329  SM-R-C0603-103J  [R0603]  105.39 91.86 0 bottom
R330  SM-R-C0603-103J  [R0603]  108.56 90.46 180 bottom
R331  SM-R-C0603-103J  [R0603]  109.32 87.92 270 bottom
R332  R/0/0402/5%  [R0402]  127.23 52.49 90 top
R333  R/0/0402/1%  [R0402]  123.42 39.41 270 bottom
R334  R/0/0402/1%  [R0402]  126.47 36.36 90 top
R335  R/4.7K/0402/5%  [R0402]  117.83 49.44 0 top
R336  NIL/R/0/0402/1%  [R0402]  130.91 30.64 135 top
R337  R/0/0402/5%  [R0402]  121.51 54.65 90 top
R338  NIL/R/3.3K/0402/1%  [R0402]  133.2 51.22 0 top
R339  R/0/0402/5%  [R0402]  122.66 54.65 90 top
R340  R/15K/0402/1%  [R0402]  128.5 38.9 270 top
R341  R/3.3K/0402/5%  [R0402]  126.09 52.49 90 top
R342  NIL/1K/0/0402/5%  [R0402]  133.2 50.08 180 top
R343  R/0/0402/5%  [R0402]  120.37 54.65 90 top
R344  NIL/R/4.7K/0402/5%  [R0402]  117.83 47.15 0 top
R345  NIL/R/0/0402/1%  [R0402]  121.01 30.14 135 top
R346  R/0/0805/1%  [R0805]  136.63 51.09 0 top
R347  R/0/0402/5%  [R0402]  119.23 54.65 90 top
R348  R/105K/0402/1%  [R0402]  113.01 45 0 bottom
R349  R/0/0402/1%  [R0402]  117.83 48.3 180 top
R350  R/100K/0402/1%  [R0402]  113.01 43.85 0 bottom
R351  R/422/0402/1%  [R0402]  135.23 41.19 0 top
R352  R/0/0402/1%  [R0402]  129.39 46.9 270 bottom
R353  NIL/R/0/0402/1%  [R0402]  133.2 48.93 180 top
R354  NI/SM-R-R0402-332J  [R0402]  99.16 35.09 180 top
R355  NI/SM-R-C0603-0R0J  [R0603]  103.61 16.17 90 top
R356  43.2  [R0603]  74.27 8.67 180 top
R357  1K  [R0603]  74.27 7.28 180 top
R358  75K  [R0402]  63.98 102.65 270 top
R359  75K  [R0402]  76.56 102.65 90 top
R360  NC/100K  [R0402]  71.35 106.84 0 top
R361  560  [R0402]  69.7 108.5 90 top
R362  NC/470K  [R0402]  69.32 90.97 180 top
R363  SM-R-R0402-330J  [R0402]  57.76 61 90 top
R364  SM-R-R0402-330J  [R0402]  59.03 61 90 top
R365  SM-R-C0603-472J  [R0603]  105 12.99 270 top
R366  NI/SM-R-R0402-103J  [R0402]  59.54 62.65 0 top
R367  NI/10K  [R0603]  32.49 84.75 0 top
R368  SM-R-C0603-0R0J  [R0603]  105 16.17 90 top
R397  43.2  [R0603]  74.27 5.88 180 top
R410  SM-R-C0603-223J  [R0603]  102.21 12.99 90 top
R414  SM-R-C0603-471J  [R0603]  103.61 12.99 270 top
R457  SM-R-C0603-102J  [R0603]  125.98 9.53 270 top
R458  SM-R-C0603-472J  [R0603]  127.38 9.53 90 top
R472  SM-R-C0603-472J  [R0603]  123.93 10.32 180 bottom
R473  SM-R-C0603-223J  [R0603]  123.93 9.05 0 bottom
R474  SM-R-C0603-471J  [R0603]  118.21 11.98 180 top
R475  SM-R-C0603-101J  [R0603]  133.83 10.32 270 top
R479  SM-R-R0402-0R0J  [R0402]  63.02 73.34 180 top
R485  SM-R-R0402-0R0J  [R0402]  63.02 72.07 180 top
R509  SM-R-C0603-101J  [R0603]  151.38 5.21 270 top
R563  SM-R-C0805-622J  [R0805]  30.42 10.81 270 top
R567  SM-R-C0805-1002F  [R0805]  28.13 10.81 90 top
R583  SM-R-C0603-682J  [R0603]  34.04 10.67 180 bottom
R584  RC_02W103JT  [R0402]  95.82 84.39 180 top
R585  RC0402JR_075K1L  [R0402]  96.28 86.04 270 top
R586  RC0603JR_074K7  [R0603]  92.72 70.8 90 top
R587  RC_05K2431KFT  [R0805]  95.64 70.04 90 top
R588  RC0402JR_070R  [R0402]  93.99 70.8 90 top
R589  RC_02W103JT  [R0402]  100.05 81.06 0 bottom
R590  RK73B1ETTP330J  [R0402]  91.96 74.86 90 top
R591  RK73H1ETTP1004F  [R0402]  91.96 77.02 270 top
R592  RC0402JR_070R  [R0402]  106.44 73.59 0 top
R593  RC0402JR_070R  [R0402]  106.44 74.74 0 top
R594  RC0402JR_070R  [R0402]  106.44 75.88 0 top
